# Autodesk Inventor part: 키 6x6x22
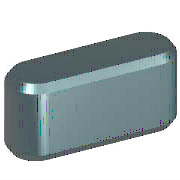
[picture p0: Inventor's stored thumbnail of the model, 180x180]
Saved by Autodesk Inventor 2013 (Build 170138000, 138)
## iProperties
IsCustomPart: 1
Created: 2012-02
Part Number: 키 6x6x22
Material: 강철, 연강
Description: 키 및 해당 키홈
Document SubType Name: Modeling
Standard: KS B 1311
Designer: mduedu
Standards Organization: KS
Language: ko-KR
Size Designation: 6 x 6 x 22
Categories: <MemberInstance><Categories><Category DisplayName="샤프트 부품" InternalName="7f7aeb1f-a693-4053-b835-cee3144e0d98" Mnemonic="SHFT"><Category DisplayName="키" Interna
Density: 7.86 g/cm^3
Mass: 5.79788 g
Surface Area: 5.294 cm^2
Volume: 0.737644 cm^3
Author: mduedu
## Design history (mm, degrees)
workplane "Work Plane1"
workplane "Work Plane2"
sketch "스케치1"
  geometry: L1 (3, 3)-(19, 3); L2 (19, -3)-(3, -3); L3 (0, 9.4)-(0, -7.4) reference; L4 (-5, 0)-(30, 0) reference; L5 (22, 0)-(22, 7); A1 r 3 centre (3, 0) between (3, 3) and (3, -3); A2 r 3 centre (19, 0) between (19, -3) and (19, 3)
  constraints: 6 end point, 5 point on circle, 4 tangent, 3 point on line, 2 centre point, 1 horizontal, 1 parallel, 1 perpendicular
  dimensions: "d0" = 3 radius of A1 (= 0.5 x PB); "d13" = 3 radius of A2 (= 0.5 x PB); "d14" = 22 distance between parallel lines of L5 L3 (= NLG)
extrude "본체1" new body sketch "스케치1" taper "d3" = 0 deg; stored distance "d4" = 10
workplane "Work Plane3"
body "Solid1"
chamfer "모따기1" distance "d8" = 0.4 (= PHH); stored, may be unused: second distance "d9" = 0.4 (= PHH), angle "d15" = 45 deg
other parameters: "d1" = -3.5 (= -PNT), "d2" = 2.5 (= PH - PNT), "NLG" = 22 [user parameter; used in 3 equation terms], "PB" = 6 [user parameter; used in 2 equation terms], "PNT" = 3.5 [user parameter; used in 2 equation terms], "PH" = 6 [user parameter; used in 1 equation term], "PHH" = 0.4 [user parameter; used in 2 equation terms], "d10" = 0, "d16" = 0, "d17" = 0, "d18" = 0, "WDMIN" = 17 [user parameter], "PLB2" = 22 (= NLG) [user parameter], "WDMAX" = 22 [user parameter], "PLB1" = 22 (= NLG) [user parameter], "RR" = 0.16 [user parameter], "PUEB" = 2.8 [user parameter]
